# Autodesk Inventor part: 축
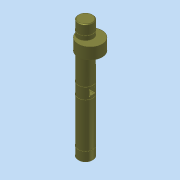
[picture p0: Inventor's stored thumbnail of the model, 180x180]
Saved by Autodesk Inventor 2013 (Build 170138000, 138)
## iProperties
Company: 한국ATC센터
Created: 2015-04
Part Number: 축
Document SubType Name: Modeling
Designer: KYOUNG IL JANG
Density: 1 g/cm^3
Material: 일반
Mass: 77.3127 g
Surface Area: 163.755 cm^2
Volume: 77.3127 cm^3
Author: KYOUNG IL JANG
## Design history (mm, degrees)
sketch "스케치1"
  geometry: C1 r 11 at (0, 0); 1 further point
  constraints: 1 centre point, 1 coincident
  dimensions: "d0" = 22 diameter of C1
extrude "돌출1" new body sketch "스케치1" stored distance "d1" = 180; taper "d2" = 0 deg
sketch "스케치2"
  geometry: L1 (-10.247, -4)-(10.247, -4); L2 (-10.247, 4)-(10.247, 4); A1 r 11 centre (0, 0) between (-10.247, -4) and (10.247, -4) reference; 1 further point
  constraints: 4 end point, 4 point on circle, 2 parallel, 1 horizontal
  dimensions: "d3" = 8 distance between parallel lines of L2 L1
extrude "돌출2" cut sketch "스케치2" stored distance "d4" = 8; taper "d5" = 0 deg
sketch "스케치3"
  geometry: 5 further points
hole "구멍1" sketch "스케치3" at (-4, 4), (4, 4), (4, -4), (-4, -4) diameter "d6" = 2; stored, may be unused: countersink angle "d10" = 90 deg, drill point angle "d12" = 118 deg; dims "d7" = 6, "d8" = 4, "d9" = 2, "d11" = 8
chamfer "모따기1" distance "d13" = 1; stored, may be unused: second distance "d14" = 2, angle "d15" = 45 deg
sketch "스케치4"
  geometry: L1 (-10, 9)-(-11, 9); L2 (-11, 9)-(-11, 7.8); L3 (-11, 7.8)-(-10, 7.8); L4 (-10, 7.8)-(-10, 9); L5 (-10, 90)-(10, 90) reference; L6 (0, -15)-(0, 90) reference; L7 (-10, 74.8)-(-11, 74.8); L8 (-11, 74.8)-(-11, 76); L9 (-11, 76)-(-10, 76); L10 (-10, 76)-(-10, 74.8); 1 further point
  constraints: 16 end point, 4 parallel, 2 equal length, 2 horizontal, 2 perpendicular, 1 collinear
  dimensions: "d16" = 7.8 distance from line of L3 point (0, 0); "d17" = 82.2 distance between parallel lines of L3 L5 (derived); "d18" = 11 distance from line of point (0, 0) L2; "d19" = 1 distance of L2.end L3.end; "d20" = 1.2 distance of L1.end L2.end; "d27" = 14 distance between parallel lines of L5 L9
revolve "회전1" sketch "스케치4" stored, may be unused: angle "d21" = 90 deg
sketch "스케치5"
  geometry: L1 (11, 52)-(-7, 52); L2 (-7, 52)-(-7, 69); L3 (-7, 69)-(11, 69); L4 (11, 69)-(11, 52); 1 further point
  constraints: 8 end point, 2 parallel, 1 horizontal, 1 perpendicular
  dimensions: "d22" = 17 distance of L3.end L1.start; "d23" = 36 diameter of L4 L2; "d24" = 7 horizontal distance of L2.end point (0, 0); "d25" = 52 distance from line of L1 point (0, 0)
revolve "회전2" sketch "스케치5" stored, may be unused: angle "d26" = 90 deg
node "솔리드1"
mirror "대칭1"
mirror "대칭2"
